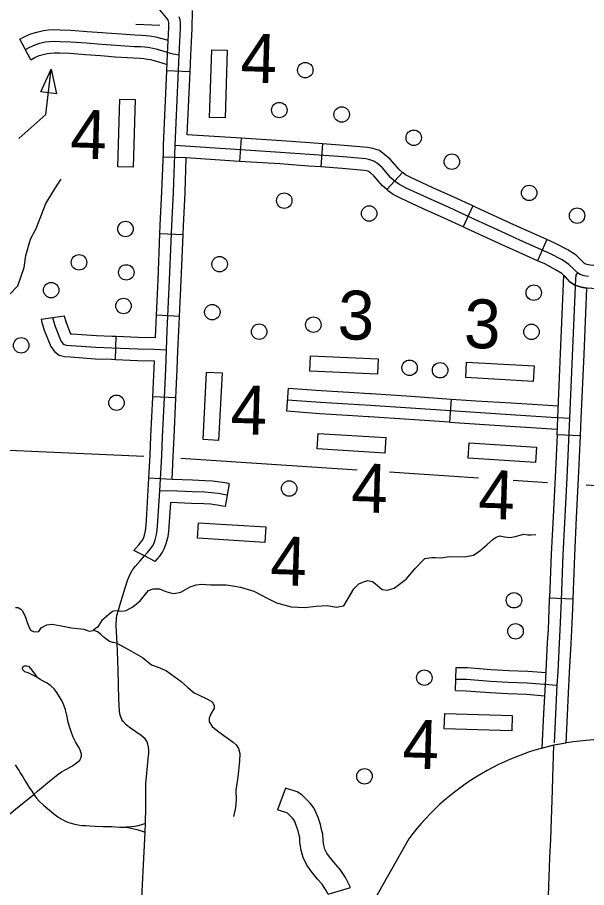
# Model space of a CAD drawing. Extents: x 653372 to 905732, y 627442 to 787275.
# Drawn here: x 694158 to 697843, y 755293 to 760924 of the extents above; entities that cross this region are included whole.
import ezdxf

# ---------------------------------------------------------------- set-up
doc = ezdxf.new("R2010")
doc.units = 0
for name, color, linetype in [('31', 7, 'Continuous'), ('32', 7, 'Continuous'), ('35', 7, 'Continuous'), ('45', 7, 'Continuous'), ('46', 7, 'Continuous'), ('5', 7, 'Continuous'), ('56', 7, 'Continuous'), ('63', 7, 'Continuous')]:
    doc.layers.add(name, color=color, linetype=linetype)

msp = doc.modelspace()

# ---------------------------------------------------------------- linework, layer by layer
at = {"layer": '31'}
for p, q in [((695902.4, 758375), (695913.3, 758524.7)), ((695913.3, 758524.7), (695913.3, 758524.7)), ((696966.6, 758454.4), (696956.4, 758304.8)), ((697801.7, 758215.6), (697651.9, 758222.3)), ((697604.2, 757166.8), (697754.1, 757161.3))]:
    msp.add_line(p, q, dxfattribs=at)
for points in [[(697783.8, 759271.2), (697774.4, 759255.2), (697770.8, 759231.7), (697731.9, 758331.6), (697714.4, 757944.7), (697689.5, 757446.1), (697678.8, 757152.2), (697670.8, 756959.5), (697665.3, 756875.4), (697656, 756690), (697651.5, 756603), (697641.8, 756414.6), (697632.9, 756230.3)], [(697674.9, 758749.7), (697696.7, 759254.2), (697735.3, 759213.3), (697768.2, 759191.7), (697809.9, 759178.4), (697843.3, 759172.8)], [(697843.3, 759172.8), (697824.8, 758743.2)], [(697651.9, 758222.3), (697657, 758334.9), (697674.9, 758749.7)], [(697824.8, 758743.2), (697806.8, 758328.3), (697801.7, 758215.6)], [(695913.3, 758524.7), (696125.3, 758509.2), (696304.7, 758498.2), (696439.3, 758489.9)], [(696439.3, 758489.9), (696445.9, 758489.5), (696707.8, 758472), (696966.6, 758454.4)], [(695907.8, 758449.9), (696120.3, 758434.4), (696300.1, 758423.4), (696441.1, 758414.6), (696702.8, 758397.2), (697123.2, 758368.6), (697350.8, 758354.3), (697613.6, 758337.9), (697731.9, 758331.6)], [(696966.6, 758454.4), (697128.1, 758443.4), (697355.5, 758429.1), (697493.1, 758420.5)], [(696430.1, 758340.2), (696295.5, 758348.5), (696115.2, 758359.6), (695902.4, 758375)], [(697493.1, 758420.5), (697660.2, 758410.1)], [(696956.4, 758304.8), (696697.7, 758322.4), (696436.3, 758339.8), (696430.1, 758340.2)], [(696956.4, 758304.8), (697118.3, 758293.7), (697346.1, 758279.4), (697483.7, 758270.8)], [(697483.7, 758270.8), (697653.6, 758260.2)], [(697651.9, 758222.3), (697639.5, 757948.3), (697626.8, 757695.3)], [(697801.7, 758215.6), (697789.3, 757941.2), (697776.6, 757687.8)], [(697626.8, 757695.3), (697614.5, 757449.4), (697604.2, 757166.8)], [(697776.6, 757687.8), (697764.4, 757442.9), (697754.1, 757161.3)], [(697578.4, 756640.6), (697581.1, 756693.8), (697590.4, 756879.7), (697595.9, 756963.5), (697603.8, 757155.2), (697604.2, 757166.8)], [(697754.1, 757161.3), (697753.7, 757149.3), (697745.7, 756955.5), (697740.2, 756871.1), (697730.9, 756686.2), (697728.2, 756632.8)], [(694284.2, 756653.4), (694263.2, 756665.2), (694245.1, 756673.3), (694227.5, 756682), (694206.9, 756689.8), (694194.5, 756701.3), (694191.9, 756708.9), (694194.2, 756717), (694196.7, 756723.7), (694205, 756728), (694217.2, 756728.7), (694229.3, 756724.7), (694242.7, 756711.6), (694264.2, 756683.5), (694273.1, 756672.5), (694284.2, 756653.4)], [(694265.4, 755895.5), (694289.2, 755917.6), (694352.4, 755970.7), (694411.7, 756019), (694444.4, 756041), (694475.5, 756059.9), (694514.4, 756081.1), (694550.7, 756106), (694561.8, 756117.9), (694569.3, 756130.4), (694572.7, 756142.5), (694572.6, 756155.2), (694569.4, 756168.6), (694563.8, 756185), (694553.1, 756203.2), (694534.8, 756235.8), (694520.4, 756265.9), (694508.6, 756295.3), (694497.8, 756326.7), (694487.7, 756362.6), (694478.4, 756408.7), (694469.8, 756444.1), (694459, 756474), (694445.1, 756502.4), (694430.5, 756527.8), (694414.5, 756554.2), (694396.4, 756578.2), (694374.7, 756599.2), (694351.7, 756615.2), (694324.2, 756629.2), (694305.1, 756640), (694284.2, 756653.4)], [(697707.9, 756228.2), (697632.1, 756213.6), (697556.1, 756195), (697566.9, 756418.4), (697576.6, 756606.8), (697578.4, 756640.6)], [(697728.2, 756632.8), (697726.4, 756599.1), (697716.7, 756410.9), (697707.9, 756228.2)], [(697645.7, 754574.8), (697616.2, 754600.1), (697591.7, 754623), (697581, 754635.9), (697576.3, 754649.4), (697574.4, 754662), (697576.3, 754724), (697588, 754967.6), (697598.1, 755303), (697606.2, 755485.2), (697611.7, 755606.4), (697623.4, 755922.7), (697625.6, 756006.4), (697632.1, 756213.6)], [(694142.9, 756087.3), (694159.9, 756062.8), (694169.7, 756047.8), (694176.4, 756035.9), (694192.5, 756010.2), (694210.9, 755978.6), (694235.6, 755939.7), (694252.2, 755915.8), (694265.4, 755895.5), (694282, 755872.1), (694300.2, 755851.2), (694327.4, 755826.4), (694378.9, 755782.3), (694414.7, 755754.2), (694441.2, 755737.1), (694465.2, 755725.2), (694482.8, 755716.5), (694498.4, 755712), (694521.3, 755705.2), (694549.7, 755699.2), (694577, 755694.8), (694601.9, 755694.1), (694626.3, 755692.3), (694662.9, 755691.2), (694713.8, 755688.7), (694769.2, 755687), (694819, 755684.5), (694862.6, 755682.7)], [(693697.3, 755840.7), (693740.5, 755786.9), (693784.4, 755741.3), (693804.9, 755726.9), (693826.9, 755714.6), (693847.6, 755707.8), (693880.4, 755700.7), (693923, 755692.8), (693954.4, 755688.3), (693980.8, 755687.5), (693995.6, 755689.1), (694013.2, 755695.7), (694034.4, 755708.8), (694076.1, 755741.2), (694146.3, 755801.2), (694234.9, 755870.9), (694265.4, 755895.5)], [(694941.2, 754748), (694957.2, 755099.5), (694985.9, 755652), (694986.9, 755707.5), (694990.1, 755812.4)], [(694986.9, 755707.5), (694967.5, 755699.9), (694940.3, 755692.6), (694918.3, 755688.2), (694897.3, 755685.7), (694862.6, 755682.7), (694894, 755676.2), (694939.5, 755666.1), (694966.3, 755658.7), (694985.9, 755652)]]:
    msp.add_lwpolyline(points, dxfattribs=at)
at = {"layer": '32'}
for p, q in [((695276.1, 760572.1), (695126.2, 760578.7)), ((695606.6, 760142.2), (695596.9, 759992.6)), ((696133.9, 760106), (696123, 759956.4)), ((695252, 760014.9), (695102.1, 760020.4)), ((696650.9, 759921), (696550.4, 759809.6)), ((697107, 759704.3), (697043.6, 759568.3)), ((695230.8, 759517.4), (695080.9, 759523.4)), ((697586.7, 759486.6), (697525.6, 759349.7)), ((694312.8, 758972.2), (694461.4, 758992.4)), ((695208.2, 758989.4), (695058.3, 758996.4)), ((694792.4, 758710.6), (694798.4, 758860.5)), ((695185.1, 758462), (695035.2, 758468.8)), ((695159.4, 757934), (695009.6, 757942)), ((695529.8, 757906.6), (695502.9, 757759)), ((696995.5, 756567.4), (696998.3, 756717.4))]:
    msp.add_line(p, q, dxfattribs=at)
for points in [[(695126.2, 760578.7), (695131, 760686.3), (695138.9, 760858.5), (695139.7, 760885.2), (695139, 760892), (695136.3, 760900.1), (695131.8, 760909.8), (695124.6, 760921.2), (695058, 761000.1), (695042.7, 761019.2)], [(695276.1, 760572.1), (695280.8, 760679.5), (695288.8, 760852.8), (695292.3, 760968.7)], [(694977.9, 757435.9), (695001.4, 757462.3), (695020.1, 757484), (695033.2, 757503.1), (695041.3, 757517.4), (695050.4, 757542.2), (695059.8, 757578.8), (695063.4, 757605.8), (695068.6, 757664.3), (695080.4, 757860.6), (695092.5, 758086.7), (695097.6, 758210.8), (695110, 758461.7), (695118.4, 758648.3), (695122.9, 758772.1), (695128.8, 758897.9), (695144, 759223.4), (695158, 759575.8), (695168.8, 759794), (695179.9, 760094.7), (695205.9, 760682.9), (695213.9, 760855.6), (695214.8, 760888.3), (695212.6, 760907.9), (695206.3, 760927.5)], [(695103.2, 760050.7), (695104.9, 760097.8), (695126.2, 760578.7)], [(695258.1, 760164.8), (695276.1, 760572.1)], [(695606.6, 760142.2), (695258.1, 760164.8)], [(696133.9, 760106), (696054.7, 760111.8), (695867.5, 760125.4), (695606.6, 760142.2)], [(697856.3, 759246.8), (697827.5, 759251.6), (697800.7, 759260.1), (697783.8, 759271.2), (697759.3, 759297.1), (697729.3, 759326), (697684.7, 759354.4), (697604.8, 759396.4), (697414.6, 759481.4), (697341.2, 759514.5), (697096.9, 759626.2), (696953, 759693.4), (696812.9, 759755.6), (696675.6, 759818.6), (696631.2, 759841.9), (696607.6, 759859), (696576.5, 759887), (696519.6, 759952.5), (696491.3, 759976.6), (696466.7, 759994.7), (696440.9, 760003.2), (696414, 760008.8), (696267.5, 760021), (696049.3, 760037), (695862.4, 760050.5), (695179.9, 760094.7)], [(696650.9, 759921), (696630.1, 759939.7), (696572.5, 760006), (696537.9, 760035.4), (696501.6, 760062.2), (696460.4, 760075.7), (696424.9, 760083.2), (696273.4, 760095.7), (696133.9, 760106)], [(695080.9, 759523.4), (695083.1, 759579.1), (695093.8, 759797.2), (695103.2, 760050.7)], [(695230.8, 759517.4), (695233, 759572.5), (695243.7, 759790.7), (695252, 760014.9)], [(695596.9, 759992.6), (695252, 760014.9)], [(696123, 759956.4), (696043.8, 759962.2), (695857.2, 759975.7), (695596.9, 759992.6)], [(696550.4, 759809.6), (696522.9, 759834.4), (696466.7, 759899), (696444.7, 759917.8), (696431.9, 759927.2), (696421.4, 759930.7), (696403.2, 759934.5), (696261.7, 759946.2), (696123, 759956.4)], [(697107, 759704.3), (696984.1, 759761.6), (696843.7, 759823.9), (696708.7, 759886), (696670.8, 759905.8), (696654.8, 759917.4), (696650.9, 759921)], [(697043.6, 759568.3), (696921.9, 759625.1), (696782, 759687.2), (696642.6, 759751.3), (696591.6, 759778), (696560.3, 759800.7), (696550.4, 759809.6)], [(697586.7, 759486.6), (697445.3, 759549.8), (697372.2, 759582.8), (697128.3, 759694.3), (697107, 759704.3)], [(697525.6, 759349.7), (697383.9, 759413), (697310.2, 759446.2), (697065.4, 759558.1), (697043.6, 759568.3)], [(695058.3, 758996.4), (695069.1, 759226.6), (695080.9, 759523.4)], [(695208.2, 758989.4), (695218.9, 759220.2), (695230.8, 759517.4)], [(698037.6, 759308.3), (697979.2, 759312.3), (697889.8, 759318.8), (697866.2, 759321.2), (697845, 759324.7), (697833.2, 759328.4), (697832.3, 759329.1), (697812.6, 759349.9), (697775.9, 759385.2), (697722.4, 759419.3), (697637.6, 759463.9), (697586.7, 759486.6)], [(698027.4, 759158.7), (697968.7, 759162.7), (697876.8, 759169.4), (697846.5, 759172.4), (697809.9, 759178.4), (697768.2, 759191.7), (697735.3, 759213.3), (697706, 759244.3), (697682.6, 759266.8), (697647, 759289.5), (697572, 759328.9), (697525.6, 759349.7)], [(694461.4, 758992.4), (694461.7, 758989.8), (694473.9, 758949.4), (694502.7, 758876.7), (694510.6, 758876.2), (694670, 758865.5), (694772.9, 758861.5), (694798.4, 758860.5)], [(695051.6, 758851.9), (695053.9, 758901.4), (695058.3, 758996.4)], [(695185.1, 758462), (695193.4, 758645.2), (695197.9, 758769), (695203.8, 758894.4), (695208.2, 758989.4)], [(694312.8, 758972.2), (694314.7, 758957.9), (694332.1, 758900.2), (694374.1, 758793.9), (694398.5, 758761.1), (694427.7, 758738.4), (694464.1, 758728.7), (694501.2, 758726.5), (694662.1, 758715.6), (694767.1, 758711.6), (694792.4, 758710.6)], [(694387.1, 758982.3), (694388.2, 758973.9), (694403, 758924.8), (694440.2, 758830.6), (694452.5, 758814), (694461.7, 758806.9), (694476.1, 758803.1), (694505.9, 758801.3), (694666, 758790.5), (694770, 758786.6), (694937.9, 758779.8), (695040.7, 758777.2), (695088, 758775.3), (695122.9, 758772.1)], [(694798.4, 758860.5), (694940.4, 758854.8), (695051.6, 758851.9)], [(694792.4, 758710.6), (694935.4, 758704.9), (695045.8, 758702)], [(695035.2, 758468.8), (695045.8, 758702)], [(695009.6, 757942), (695017.5, 758090.2), (695022.7, 758214.2), (695035.1, 758465.3), (695035.2, 758468.8)], [(695159.4, 757934.3), (695167.4, 758083.1), (695172.5, 758207.4), (695184.9, 758458.2), (695185.1, 758462)], [(695049.6, 757403.3), (694981.7, 757440.1), (694911.2, 757473.8), (694945, 757511.7), (694960.6, 757529.8), (694969.5, 757542.8), (694973, 757548.9), (694978.7, 757564.6), (694986.1, 757593.2), (694988.9, 757614.1), (694993.8, 757669.9), (695005.5, 757864.9), (695009.6, 757942)], [(695529.9, 757906.6), (695515.7, 757909.2), (695471.7, 757916.8), (695421.7, 757922.3), (695373.9, 757926.1), (695292.3, 757929.3), (695159.4, 757934.3)], [(695516.4, 757832.8), (695502.6, 757835.3), (695461.2, 757842.5), (695414.6, 757847.6), (695369.5, 757851.2), (695289.4, 757854.4), (695193.8, 757858), (695080.4, 757860.6)], [(695049.6, 757403.3), (695079.6, 757438.1), (695096.9, 757463.4), (695109.6, 757485.9), (695122.1, 757519.9), (695133.6, 757564.4), (695138, 757597.6), (695143.4, 757658.8), (695150.9, 757784.5)], [(695502.9, 757759), (695489.4, 757761.5), (695450.7, 757768.2), (695407.6, 757773), (695365, 757776.3), (695286.5, 757779.4), (695150.9, 757784.5)], [(694990.1, 755812.4), (694990.4, 755963.6), (695000.9, 756078.8), (695005.8, 756126.6), (695008.2, 756162.1), (695010.2, 756181.5), (695007.3, 756201.7), (695003.7, 756219.9), (694996, 756241), (694984.6, 756254.6), (694960.2, 756276.9), (694890.7, 756324.2), (694862.8, 756346.6), (694844.6, 756366), (694835.4, 756381.5), (694826.2, 756401.3), (694821.1, 756416.8), (694819.6, 756435.6), (694815, 756513.1), (694811.6, 756700.4), (694806.1, 756820.9), (694804.2, 756873.1), (694800.2, 756947.6), (694798.7, 756990.1), (694799.4, 757035.3), (694802, 757054), (694811.2, 757081.6), (694825.3, 757134), (694855.3, 757231.9), (694873.7, 757285.6), (694887.9, 757320.3), (694901.2, 757344.9), (694920, 757370.1), (694953.1, 757408.1), (694981.7, 757440.1)], [(696998.3, 756717.4), (697070.2, 756716), (697225.9, 756703.9), (697339.9, 756697.8), (697462.4, 756693.3), (697580.6, 756683.9)], [(696996.9, 756642.4), (697066.6, 756641.1), (697220.9, 756629.1), (697336.5, 756622.9), (697458, 756618.5), (697651.5, 756603)], [(696995.5, 756567.4), (697063, 756566.1), (697216, 756554.2), (697333.1, 756547.9), (697453.7, 756543.6), (697572.9, 756534)]]:
    msp.add_lwpolyline(points, dxfattribs=at)
at = {"layer": '35'}
for points in [[(694106.9, 759130.4), (694160.4, 759186.3), (694202.3, 759305.5), (694212.3, 759383.8), (694242.3, 759488.3), (694280.8, 759558.1), (694342.6, 759720.7), (694411.1, 759831.8), (694441.2, 759876.9)], [(694821.7, 757082.5), (694851.3, 757083.9), (694863.5, 757086.6), (694905.9, 757110.4), (694952.9, 757149.3), (694987.6, 757191.4), (695007.7, 757214.4), (695037.3, 757226), (695079, 757226.2), (695118.8, 757209.7), (695149.1, 757200.4), (695171.2, 757195.6), (695216, 757205.4), (695276.8, 757238.3), (695314.8, 757252.5), (695352.5, 757256.9), (695409.3, 757251), (695509.4, 757252.2), (695552.3, 757245.3), (695603.5, 757236.8), (695688.9, 757210.6), (695779.3, 757163.4), (695835.5, 757135.3), (695929.7, 757110.2), (696016.4, 757104.8), (696091.8, 757113.7), (696164.7, 757117.7), (696222.9, 757106.4), (696271.4, 757116.1), (696336.4, 757225.7), (696369.4, 757258.4), (696405.3, 757272.5), (696427, 757279.1), (696457.9, 757274.4), (696474.4, 757261.1), (696519.8, 757221.8), (696553, 757218.1), (696597.9, 757230.6), (696674.7, 757288.1), (696733.9, 757358.7), (696779.8, 757406), (696796.9, 757422.2), (696840.3, 757429.2), (696865.3, 757429.8), (696902.7, 757425.9), (696953.8, 757435.5), (697053.8, 757432.5), (697111.1, 757443.3), (697152.3, 757471.3), (697196.6, 757511.7), (697239.4, 757546.6), (697257.8, 757559.9), (697284.5, 757568.9), (697310.8, 757562.5), (697346.8, 757558.6), (697383.1, 757564.5), (697435, 757579.6), (697462.7, 757576), (697484.1, 757576.5), (697514.3, 757577.9)], [(694146.6, 757105), (694164.3, 757104.5), (694180.3, 757095.1), (694188.9, 757086), (694205.6, 757053), (694215.3, 757030.6), (694222, 757008.2), (694230.2, 756987.3), (694244.1, 756958.8), (694266.7, 756947.7), (694296.3, 756949.8), (694313.3, 756972.9), (694349.3, 756992.5), (694380.5, 756997.5), (694431.9, 756988.6), (694508.3, 756974.5), (694589.2, 756964.7), (694622.8, 756951.8), (694648.8, 756955.5)], [(694821.7, 757082.5), (694789.3, 757084.2), (694773.6, 757079.5), (694750.9, 757060.3), (694704.7, 757021.8), (694676, 756977.6), (694661.7, 756966.2), (694648.8, 756955.5)], [(694802.2, 756874.6), (694775.7, 756878.5), (694755.3, 756885.8), (694720.6, 756910.5), (694699, 756930.3), (694680.3, 756945.7), (694666.4, 756952), (694648.8, 756955.5)], [(694802.2, 756874.6), (694893.8, 756825.5), (694969.3, 756782.4), (695027, 756734.8), (695079.5, 756714), (695123.3, 756695), (695218.7, 756627.1), (695261.9, 756587.4), (695302.2, 756553.7), (695331.4, 756541), (695388.1, 756512.7), (695420.1, 756494), (695432.6, 756470), (695432.1, 756452.2), (695413.5, 756421.8), (695400.6, 756388.2), (695400, 756366), (695418.3, 756335.9), (695445.7, 756312.9), (695494.8, 756276), (695555.5, 756232.8), (695574.2, 756216.2), (695589.8, 756193.5)], [(695589.8, 756193.5), (695597.7, 756160.8), (695596.2, 756110.6), (695585.7, 756007.5), (695572.8, 755922.2), (695575.4, 755861.5), (695570.9, 755809.9), (695557.3, 755752.7)]]:
    msp.add_lwpolyline(points, dxfattribs=at)
at = {"layer": '45'}
for p, q in [((694245.5, 760650.5), (694174.2, 760782.5)), ((696169.8, 755250.5), (696313.8, 755292.6))]:
    msp.add_line(p, q, dxfattribs=at)
for points in [[(694174.2, 760782.5), (694206.6, 760800), (694246.2, 760816.9), (694283.3, 760829.7), (694326.5, 760839.4), (694359.7, 760843.4), (694394, 760845.3), (694434.8, 760844.1), (694505.2, 760842), (694610.4, 760833.8), (694707.7, 760826.8), (694733.4, 760824.7)], [(694733.4, 760824.7), (694802.9, 760819.1), (694917.7, 760811.6), (694962.3, 760810.3), (694991, 760808), (695013.3, 760805.4), (695028.8, 760802.5), (695051.5, 760798.2), (695135.2, 760777.7)], [(694209.9, 760716.5), (694239.3, 760732.4), (694273.2, 760746.9), (694303.8, 760757.5), (694339.2, 760765.4), (694366.3, 760768.7), (694395, 760770.3), (694432.6, 760769.1), (694501.2, 760767.1), (694604.9, 760759.1), (694702, 760752), (694797.4, 760744.3), (694914.2, 760736.7), (694958.3, 760735.4), (694983.6, 760733.4), (695001.9, 760731.2), (695014.9, 760728.7), (695035.7, 760724.8), (695054.7, 760720.2), (695092.6, 760709.2), (695135.2, 760696.5), (695164.4, 760689.5), (695181.5, 760685.7), (695192.9, 760683.7), (695205.9, 760682.9)], [(694245.5, 760650.5), (694271.9, 760664.8), (694300.2, 760676.9), (694324.3, 760685.2), (694352, 760691.4), (694372.9, 760693.9), (694395.9, 760695.2), (694430.3, 760694.2), (694497.2, 760692.2), (694599.3, 760684.3), (694696.2, 760677.3), (694721.2, 760675.2)], [(694721.2, 760675.2), (694791.9, 760669.5), (694910.6, 760661.7), (694954.2, 760660.4), (694976.2, 760658.7), (694990.6, 760657), (695001.1, 760655), (695019.8, 760651.5), (695035.4, 760647.7), (695071.4, 760637.3), (695128.1, 760620.3)]]:
    msp.add_lwpolyline(points, dxfattribs=at)
at = {"layer": '46'}
for points in [[(696313.8, 755292.6), (696282.5, 755356.9), (696247.7, 755408.9), (696217, 755444), (696179.5, 755490.7), (696161.8, 755514.9), (696149.6, 755541.4), (696141.5, 755567.7), (696137, 755599.2), (696134.8, 755638.6), (696127.6, 755668), (696119.7, 755700), (696104.9, 755745.9), (696090.8, 755780.3), (696077.6, 755808.2), (696053.6, 755840), (696022.4, 755871.8), (695999.5, 755893.3), (695968.5, 755912.4), (695943.8, 755921.2), (695918.9, 755928.5), (695893.5, 755936.5), (695842.8, 755795.2)], [(696169.8, 755250.5), (696152.9, 755280.8), (696128.3, 755317.5), (696102, 755347.6), (696060.4, 755399.5), (696031.9, 755438.6), (696009.2, 755487.6), (695994.7, 755534.9), (695987.7, 755584.3), (695985.8, 755616.4), (695982, 755632.2), (695975.4, 755658.9), (695964, 755694.3), (695953.5, 755719.6), (695948.5, 755730.2), (695939.7, 755742), (695917.5, 755764.5), (695908, 755773.5), (695903.2, 755776.4), (695897.3, 755778.6), (695875.3, 755785), (695842.8, 755795.2)]]:
    msp.add_lwpolyline(points, dxfattribs=at)
at = {"layer": '5'}
for points in [[(693424.2, 758154.6), (694977.6, 758085.2)], [(695216, 758072.6), (696358.2, 757996.9)], [(696568, 757983), (697143.6, 757944.8)], [(697367.3, 757930), (697589.3, 757915.3)], [(697839.9, 757898.6), (699020.7, 757820.4)]]:
    msp.add_lwpolyline(points, dxfattribs=at)
at = {"layer": '56'}
for p, q in [((694309.2, 760442.5), (694377.5, 760588.6)), ((694377.5, 760588.6), (694410.5, 760430.7)), ((694410.5, 760430.7), (694309.2, 760442.5))]:
    msp.add_line(p, q, dxfattribs=at)
for points in [[(694925.4, 760881.4), (695081.1, 760874.2)], [(694168, 760140.8), (694343.3, 760295.3), (694377.5, 760588.6)]]:
    msp.add_lwpolyline(points, dxfattribs=at)
for points in [[(695416.1, 760714.6), (695516.1, 760711.6), (695503, 760274.3), (695403, 760277.3)], [(694821.8, 760395.2), (694921.8, 760392.2), (694908.6, 759954.9), (694808.7, 759957.9)], [(696051.5, 758634.9), (696055.9, 758734.8), (696493, 758715.6), (696488.6, 758615.7)], [(697060.7, 758593.9), (697066.4, 758693.7), (697503.2, 758668.6), (697497.5, 758568.8)], [(695383.1, 758628.6), (695483, 758623.4), (695460.2, 758186.5), (695360.3, 758191.7)], [(696099.8, 758132.3), (696106, 758232.1), (696542.7, 758204.8), (696536.4, 758105)], [(697076.4, 758071.1), (697082.7, 758170.9), (697519.3, 758143.6), (697513.1, 758043.8)], [(695324, 757554.3), (695330.3, 757654.1), (695766.9, 757626.8), (695760.7, 757527)], [(696922, 756320.2), (696925, 756420.2), (697362.3, 756407), (697359.3, 756307.1)]]:
    msp.add_lwpolyline(points, close=True, dxfattribs=at)
for centre in [(696022, 760583.1), (695853.9, 760324.5), (696257.8, 760295.7), (696724.2, 760145.3), (696970.6, 759990.5), (697471.4, 759788.4), (695886.1, 759738.5), (696435.6, 759655.4), (697781.7, 759641.2), (694858.4, 759554.9), (694557.5, 759339), (694863.4, 759274), (695467.6, 759327.3), (694377.1, 759159.3), (697501.2, 759142.5), (694845.3, 759056.9), (695420.1, 759016.7), (696074.4, 758935.6), (695723.8, 758890.3), (697486.5, 758889.4), (694182.8, 758801.9), (696697.3, 758656.8), (696894.9, 758640.8), (694800, 758430.4), (695918, 757875.1), (697373.3, 757152.1), (697383.4, 756951.2), (696792.8, 756651), (696405.1, 756012.7)]:
    msp.add_circle(centre, 50, dxfattribs=at)
at = {"layer": '63'}
msp.add_line((696691.9, 755608.4), (693630.8, 750188.2), dxfattribs=at)
msp.add_arc((697973.1, 754651), 1599.3, 46.1475, 143.2307, dxfattribs=at)

# ---------------------------------------------------------------- texts
at = {"layer": '56'}
for s, p in [('4', (695599.5, 760505.3)), ('4', (694498, 760012.4)), ('3', (696228.9, 758842.5)), ('3', (697046.4, 758786.1)), ('4', (695535.2, 758229.2)), ('4', (696316.5, 757723.2)), ('4', (697138.9, 757680.2)), ('4', (695792.5, 757250.9)), ('4', (696648.1, 756065))]:
    msp.add_text(s, height=316.8, rotation=358.28, dxfattribs=at).set_placement(p)

doc.saveas('drawing.dxf')
